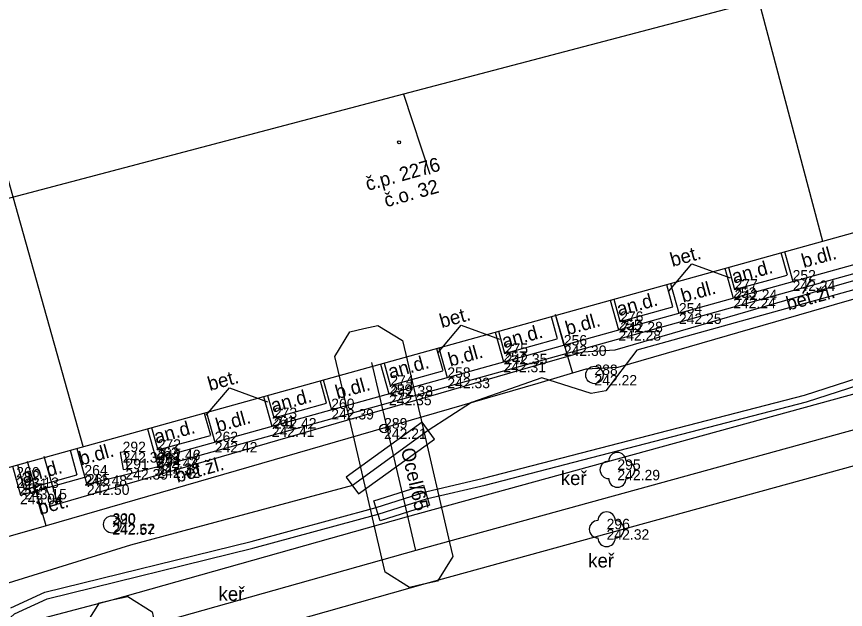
# Model space of a CAD drawing. Extents: x -599432 to -598680, y -1159407 to -1158632.
# Drawn here: x -599106.02 to -599082.18, y -1158901.06 to -1158883.99 of the extents above; entities that cross this region are included whole.
import ezdxf

# ---------------------------------------------------------------- set-up
doc = ezdxf.new("R2010")
doc.units = 0
for name, color, linetype in [('0004 VY - Body podrobné', 7, 'Continuous'), ('0005 VY - Body podrobné - čísla', 7, 'Continuous'), ('0006 VY - Body podrobné - výšky', 7, 'Continuous'), ('0007 ZA - Budova - zděná', 7, 'Continuous'), ('0010 ZA - Budova - označení', 7, 'Continuous'), ('0031 ZA - Ostatní rozhraní', 7, 'Continuous'), ('0032 TE - Popis povrchu', 7, 'Continuous'), ('0035 ZA - Strom - značka', 7, 'Continuous'), ('0036 TE - Strom - popis', 7, 'Continuous'), ('0049 TE - Orientační _ popisná čísla', 7, 'Continuous'), ('0075 ZA - BVK - kanalizace - buňky', 7, 'Continuous'), ('0092 ZA - RWE - plynovod - buňky', 7, 'Continuous'), ('0116 PV - budova převzatá z mapy', 7, 'Continuous'), ('0301 PV - RWE - popis', 7, 'Continuous'), ('0302 PV - RWE - NTL', 7, 'Continuous'), ('0303 PV - RWE - NTL přípojka', 7, 'Continuous'), ('0308 PV - RWE - ochranné pásmo', 7, 'Continuous'), ('0354 PV - EON - VN', 7, 'Continuous'), ('0367 PV - EON - VN chránička', 7, 'Continuous'), ('0454 PV - O2 - kabel zaměřený', 7, 'Continuous'), ('0454 PV - PODA -  vedeni budoucnost', 7, 'Continuous'), ('0455 PV - O2 - kabel nezaměřený', 7, 'Continuous'), ('0552 PV - NETBOX - vedení', 7, 'Continuous'), ('0553 PV - NETBOX - chranička', 7, 'Continuous')]:
    doc.layers.add(name, color=color, linetype=linetype)

msp = doc.modelspace()

# ---------------------------------------------------------------- linework, layer by layer
at = {"layer": '0004 VY - Body podrobné'}
for p, q in [((-599083.7, -1158891.59), (-599083.7, -1158891.59)), ((-599085.37, -1158891.85), (-599085.37, -1158891.85)), ((-599085.41, -1158892.09), (-599085.41, -1158892.09)), ((-599086.97, -1158892.54), (-599086.97, -1158892.54)), ((-599088.66, -1158892.78), (-599088.66, -1158892.78)), ((-599088.71, -1158893.02), (-599088.71, -1158893.02)), ((-599090.28, -1158893.46), (-599090.28, -1158893.46)), ((-599091.98, -1158893.7), (-599091.98, -1158893.7)), ((-599092.02, -1158893.93), (-599092.02, -1158893.93)), ((-599093.63, -1158894.39), (-599093.63, -1158894.39)), ((-599089.4, -1158894.31), (-599089.4, -1158894.31)), ((-599095.27, -1158894.62), (-599095.27, -1158894.62)), ((-599095.31, -1158894.88), (-599095.31, -1158894.88)), ((-599096.97, -1158895.29), (-599096.97, -1158895.29)), ((-599098.62, -1158895.55), (-599098.62, -1158895.55)), ((-599098.68, -1158895.79), (-599098.68, -1158895.79)), ((-599095.45, -1158895.85), (-599095.45, -1158895.85)), ((-599100.32, -1158896.24), (-599100.32, -1158896.24)), ((-599102.97, -1158896.53), (-599102.97, -1158896.53)), ((-599101.96, -1158896.46), (-599101.96, -1158896.46)), ((-599102.02, -1158896.69), (-599102.02, -1158896.69)), ((-599101.98, -1158896.85), (-599101.98, -1158896.85)), ((-599102.89, -1158897.02), (-599102.89, -1158897.02)), ((-599101.97, -1158896.97), (-599101.97, -1158896.97)), ((-599088.74, -1158897.04), (-599088.74, -1158897.04)), ((-599104.07, -1158897.2), (-599104.07, -1158897.2)), ((-599105.8, -1158897.59), (-599105.8, -1158897.59)), ((-599104, -1158897.46), (-599104, -1158897.46)), ((-599105.92, -1158897.73), (-599105.92, -1158897.73)), ((-599103.26, -1158898.59), (-599103.26, -1158898.59)), ((-599103.27, -1158898.61), (-599103.27, -1158898.61)), ((-599089.05, -1158898.75), (-599089.05, -1158898.75))]:
    msp.add_line(p, q, dxfattribs=at)
at = {"layer": '0007 ZA - Budova - zděná'}
msp.add_line((-599122.72, -1158901.55), (-599062.29, -1158884.74), dxfattribs=at)
at = {"layer": '0010 ZA - Budova - označení'}
msp.add_circle((-599095.018, -1158887.612), 0.0438, dxfattribs=at)
at = {"layer": '0031 ZA - Ostatní rozhraní'}
for p, q in [((-599102.013, -1158896.716), (-599063.128, -1158885.899)), ((-599101.946, -1158896.957), (-599063.061, -1158886.14)), ((-599084.036, -1158890.789), (-599083.859, -1158891.425)), ((-599083.931, -1158890.76), (-599083.692, -1158891.617)), ((-599085.647, -1158891.237), (-599085.409, -1158892.095)), ((-599085.548, -1158891.21), (-599085.371, -1158891.846)), ((-599085.369, -1158891.854), (-599083.856, -1158891.433)), ((-599087.211, -1158891.672), (-599086.973, -1158892.53)), ((-599087.329, -1158891.705), (-599087.152, -1158892.341)), ((-599088.842, -1158892.126), (-599088.665, -1158892.762)), ((-599088.95, -1158892.156), (-599088.712, -1158893.014)), ((-599088.663, -1158892.77), (-599087.15, -1158892.349)), ((-599090.648, -1158892.629), (-599090.472, -1158893.264)), ((-599090.521, -1158892.593), (-599090.283, -1158893.451)), ((-599092.258, -1158893.076), (-599092.019, -1158893.934)), ((-599092.161, -1158893.049), (-599091.984, -1158893.685)), ((-599091.982, -1158893.693), (-599090.469, -1158893.272)), ((-599093.94, -1158893.544), (-599093.763, -1158894.18)), ((-599093.871, -1158893.525), (-599093.632, -1158894.382)), ((-599095.557, -1158893.994), (-599095.318, -1158894.851)), ((-599095.452, -1158893.965), (-599095.275, -1158894.601)), ((-599095.273, -1158894.609), (-599093.761, -1158894.188)), ((-599097.289, -1158894.476), (-599097.112, -1158895.112)), ((-599097.203, -1158894.452), (-599096.965, -1158895.309)), ((-599098.919, -1158894.929), (-599098.681, -1158895.787)), ((-599098.802, -1158894.897), (-599098.625, -1158895.532)), ((-599098.623, -1158895.541), (-599097.11, -1158895.12)), ((-599100.624, -1158895.404), (-599100.447, -1158896.039)), ((-599100.558, -1158895.385), (-599100.319, -1158896.243)), ((-599102.252, -1158895.856), (-599101.946, -1158896.957)), ((-599102.137, -1158895.824), (-599101.958, -1158896.468)), ((-599101.958, -1158896.468), (-599100.445, -1158896.047)), ((-599104.289, -1158896.423), (-599104, -1158897.46)), ((-599104.48, -1158896.476), (-599104.284, -1158897.182)), ((-599105.993, -1158896.897), (-599105.797, -1158897.6)), ((-599106.14, -1158896.938), (-599105.91, -1158897.767)), ((-599101.946, -1158896.957), (-599104, -1158897.46)), ((-599105.91, -1158897.767), (-599104.058, -1158897.252)), ((-599105.796, -1158897.603), (-599104.284, -1158897.182))]:
    msp.add_line(p, q, dxfattribs=at)
at = {"layer": '0032 TE - Popis povrchu'}
for p, q in [((-599087.263, -1158891.899), (-599086.598, -1158891.108)), ((-599086.598, -1158891.108), (-599085.5, -1158891.512)), ((-599083.404, -1158891.961), (-599083.17, -1158891.554)), ((-599093.896, -1158893.662), (-599093.231, -1158892.871)), ((-599093.231, -1158892.871), (-599092.133, -1158893.275)), ((-599100.566, -1158895.47), (-599099.9, -1158894.679)), ((-599099.9, -1158894.679), (-599098.803, -1158895.082)), ((-599100.979, -1158896.916), (-599100.745, -1158896.508)), ((-599105.193, -1158897.499), (-599105.036, -1158897.898))]:
    msp.add_line(p, q, dxfattribs=at)
at = {"layer": '0035 ZA - Strom - značka'}
for centre in [(-599088.74, -1158897.04), (-599089.05, -1158898.75)]:
    msp.add_circle(centre, 0.00025, dxfattribs=at)
for centre, start, end in [((-599088.74, -1158896.79), 0, 180), ((-599088.99, -1158897.04), 90, 270), ((-599088.49, -1158897.04), 270, 90), ((-599088.74, -1158897.29), 180, 360), ((-599089.05, -1158898.5), 0, 180), ((-599089.3, -1158898.75), 90, 270), ((-599088.8, -1158898.75), 270, 90), ((-599089.05, -1158899), 180, 360)]:
    msp.add_arc(centre, 0.25, start, end, dxfattribs=at)
at = {"layer": '0075 ZA - BVK - kanalizace - buňky'}
msp.add_lwpolyline([(-599103.039, -1158896.541), (-599102.959, -1158897.031), (-599102.821, -1158897.009), (-599102.901, -1158896.519)], close=True, dxfattribs=at)
for centre in [(-599089.4, -1158894.31), (-599103.27, -1158898.61)]:
    msp.add_circle(centre, 0.25, dxfattribs=at)
at = {"layer": '0092 ZA - RWE - plynovod - buňky'}
msp.add_circle((-599095.45, -1158895.85), 0.125, dxfattribs=at)
at = {"layer": '0116 PV - budova převzatá z mapy'}
for p, q in [((-599086.46, -1158876.8), (-599082.837, -1158890.456)), ((-599104.106, -1158896.372), (-599107.93, -1158882.74))]:
    msp.add_line(p, q, dxfattribs=at)
at = {"layer": '0302 PV - RWE - NTL'}
msp.add_lwpolyline([(-599042.76, -1158885.49), (-599068.42, -1158892.17), (-599094.54, -1158899.36), (-599103.01, -1158901.75), (-599109.28, -1158903.4), (-599121.29, -1158906.57), (-599128.03, -1158908.44), (-599139.52, -1158911.687), (-599140.38, -1158911.93), (-599166.16, -1158919.18), (-599194.33, -1158927.1), (-599199.24, -1158928.46), (-599225.65, -1158935.9)], dxfattribs=at)
at = {"layer": '0303 PV - RWE - NTL přípojka'}
msp.add_lwpolyline([(-599094.54, -1158899.36), (-599095.36, -1158895.83), (-599095.8, -1158893.95)], dxfattribs=at)
at = {"layer": '0308 PV - RWE - ochranné pásmo'}
for points in [[(-599166.431, -1158918.217), (-599140.651, -1158910.968), (-599139.792, -1158910.725), (-599128.3, -1158907.477), (-599121.551, -1158905.605), (-599109.535, -1158902.433), (-599103.273, -1158900.785), (-599094.808, -1158898.397), (-599068.679, -1158891.204), (-599043.012, -1158884.522)], [(-599042.508, -1158886.458), (-599068.161, -1158893.136), (-599094.272, -1158900.323), (-599102.747, -1158902.715), (-599109.025, -1158904.367), (-599121.029, -1158907.535), (-599127.76, -1158909.403), (-599139.248, -1158912.649), (-599140.109, -1158912.892), (-599165.889, -1158920.143)]]:
    msp.add_lwpolyline(points, dxfattribs=at)
for points in [[(-599095.42, -1158899.989), (-599095.514, -1158899.586), (-599096.334, -1158896.057), (-599096.774, -1158894.178), (-599096.868, -1158893.775), (-599096.431, -1158893.07), (-599096.028, -1158892.976), (-599095.625, -1158892.882), (-599094.92, -1158893.319), (-599094.826, -1158893.722), (-599094.386, -1158895.603), (-599093.566, -1158899.134), (-599093.472, -1158899.537), (-599093.911, -1158900.24), (-599094.314, -1158900.334), (-599094.717, -1158900.428)], [(-599102.124, -1158901.128), (-599102.034, -1158901.532), (-599101.77, -1158902.713), (-599101.68, -1158903.117), (-599102.124, -1158903.817), (-599102.528, -1158903.907), (-599102.932, -1158903.997), (-599103.632, -1158903.553), (-599103.722, -1158903.149), (-599103.986, -1158901.968), (-599104.076, -1158901.564), (-599103.632, -1158900.864), (-599103.228, -1158900.774), (-599102.824, -1158900.684)]]:
    msp.add_lwpolyline(points, close=True, dxfattribs=at)
at = {"layer": '0354 PV - EON - VN'}
for points in [[(-599106.185, -1158901.015), (-599105.203, -1158900.565), (-599099.275, -1158899.103), (-599095.678, -1158898.124), (-599094.257, -1158897.674), (-599092.594, -1158897.283), (-599083.358, -1158894.894), (-599075.013, -1158892.195), (-599069.806, -1158890.267), (-599068.426, -1158889.707), (-599062.435, -1158887.486)], [(-599100.02, -1158930.068), (-599101.253, -1158923.926), (-599102.806, -1158918.536), (-599103.846, -1158916.105), (-599105.285, -1158911.524), (-599105.454, -1158911.165), (-599105.752, -1158909.781), (-599105.72, -1158909.453), (-599106.602, -1158905.369), (-599106.913, -1158903.886), (-599107.107, -1158903.206), (-599106.839, -1158901.863), (-599106.075, -1158901.185), (-599105.137, -1158900.755), (-599099.225, -1158899.297), (-599095.622, -1158898.316), (-599094.203, -1158897.866), (-599092.546, -1158897.477), (-599083.302, -1158895.086), (-599074.947, -1158892.385), (-599069.734, -1158890.453), (-599068.354, -1158889.893), (-599062.365, -1158887.674)]]:
    msp.add_lwpolyline(points, dxfattribs=at)
at = {"layer": '0367 PV - EON - VN chránička'}
for p, q in [((-599095.741, -1158897.934), (-599094.321, -1158897.484)), ((-599094.321, -1158897.484), (-599094.139, -1158898.056)), ((-599095.559, -1158898.506), (-599095.741, -1158897.934)), ((-599094.139, -1158898.056), (-599095.559, -1158898.506))]:
    msp.add_line(p, q, dxfattribs=at)
at = {"layer": '0454 PV - O2 - kabel zaměřený'}
for points in [[(-599044.86, -1158857.4), (-599039.92, -1158875.08), (-599038.76, -1158879.22), (-599057.85, -1158884.88), (-599061.72, -1158885.91), (-599062.01, -1158885.99), (-599082.28, -1158891.7), (-599088.81, -1158893.6), (-599089.73, -1158893.65), (-599091.17, -1158894.07)], [(-599091.17, -1158894.07), (-599104.83, -1158898.03), (-599105.23, -1158896.66)]]:
    msp.add_lwpolyline(points, dxfattribs=at)
at = {"layer": '0454 PV - PODA -  vedeni budoucnost'}
msp.add_line((-599090.528, -1158892.559), (-599090.032, -1158894.259), dxfattribs=at)
for points in [[(-599105.17, -1158898.649), (-599117.1, -1158902.075), (-599122.583, -1158904.816), (-599124.582, -1158905.375), (-599125.445, -1158902.506), (-599126.295, -1158901.085), (-599125.775, -1158896.452), (-599128.034, -1158888.659), (-599130.281, -1158879.673), (-599132.87, -1158880.447), (-599147.378, -1158884.773)], [(-599038.146, -1158879.559), (-599057.715, -1158885.361), (-599061.589, -1158886.393), (-599061.876, -1158886.472), (-599082.142, -1158892.181), (-599088.725, -1158894.096), (-599089.645, -1158894.146), (-599091.03, -1158894.55)], [(-599091.031, -1158894.55), (-599105.17, -1158898.649), (-599105.71, -1158896.8)]]:
    msp.add_lwpolyline(points, dxfattribs=at)
at = {"layer": '0455 PV - O2 - kabel nezaměřený'}
for points in [[(-599070.97, -1158879.92), (-599094.89, -1158886.23)], [(-599094.89, -1158886.23), (-599109.75, -1158890.15)], [(-599094.89, -1158886.23), (-599094.13, -1158888.53)]]:
    msp.add_lwpolyline(points, dxfattribs=at)
at = {"layer": '0552 PV - NETBOX - vedení'}
msp.add_lwpolyline([(-599081.59, -1158891.76), (-599088.18, -1158893.6), (-599088.18, -1158893.6), (-599089.07, -1158894.77), (-599089.07, -1158894.77), (-599089.49, -1158894.84), (-599089.49, -1158894.84), (-599090.91, -1158894.39), (-599090.91, -1158894.39), (-599092.94, -1158895.1), (-599092.94, -1158895.1), (-599094.18, -1158895.91), (-599094.18, -1158895.91), (-599096.36, -1158897.49), (-599096.36, -1158897.49), (-599102.74, -1158899.21), (-599102.74, -1158899.21), (-599108.37, -1158900.95)], dxfattribs=at)
at = {"layer": '0553 PV - NETBOX - chranička'}
msp.add_lwpolyline([(-599094.356, -1158895.667), (-599096.536, -1158897.247), (-599096.184, -1158897.733), (-599094.004, -1158896.153), (-599094.356, -1158895.667)], dxfattribs=at)

# ---------------------------------------------------------------- texts
at = {"layer": '0005 VY - Body podrobné - čísla'}
for s, p in [('252', (-599083.7, -1158891.59)), ('277', (-599085.37, -1158891.85)), ('253', (-599085.41, -1158892.09)), ('254', (-599086.97, -1158892.54)), ('276', (-599088.66, -1158892.78)), ('255', (-599088.71, -1158893.02)), ('256', (-599090.28, -1158893.46)), ('275', (-599091.98, -1158893.7)), ('257', (-599092.02, -1158893.93)), ('288', (-599089.4, -1158894.31)), ('258', (-599093.63, -1158894.39)), ('274', (-599095.27, -1158894.62)), ('259', (-599095.31, -1158894.88)), ('260', (-599096.97, -1158895.29)), ('273', (-599098.62, -1158895.55)), ('261', (-599098.68, -1158895.79)), ('289', (-599095.45, -1158895.85)), ('262', (-599100.32, -1158896.24)), ('272', (-599101.96, -1158896.46)), ('292', (-599102.97, -1158896.53)), ('263', (-599102.02, -1158896.69)), ('293', (-599101.98, -1158896.85)), ('294', (-599101.97, -1158896.97)), ('264', (-599104.07, -1158897.2)), ('291', (-599102.89, -1158897.02)), ('295', (-599088.74, -1158897.04)), ('266', (-599106.03, -1158897.26)), ('265', (-599104, -1158897.46)), ('271', (-599105.8, -1158897.59)), ('267', (-599105.92, -1158897.73)), ('290', (-599103.27, -1158898.61)), ('320', (-599103.26, -1158898.59)), ('296', (-599089.05, -1158898.75))]:
    msp.add_text(s, height=0.3, dxfattribs=at).set_placement(p)
at = {"layer": '0006 VY - Body podrobné - výšky'}
for s, p in [('242.24', (-599083.7, -1158891.89)), ('242.24', (-599085.37, -1158892.15)), ('242.24', (-599085.41, -1158892.39)), ('242.25', (-599086.97, -1158892.84)), ('242.28', (-599088.66, -1158893.08)), ('242.28', (-599088.71, -1158893.32)), ('242.30', (-599090.28, -1158893.76)), ('242.35', (-599091.98, -1158894)), ('242.31', (-599092.02, -1158894.23)), ('242.33', (-599093.63, -1158894.69)), ('242.22', (-599089.4, -1158894.61)), ('242.38', (-599095.27, -1158894.92)), ('242.35', (-599095.31, -1158895.18)), ('242.39', (-599096.97, -1158895.59)), ('242.42', (-599098.62, -1158895.85)), ('242.41', (-599098.68, -1158896.09)), ('242.21', (-599095.45, -1158896.15)), ('242.42', (-599100.32, -1158896.54)), ('242.39', (-599102.97, -1158896.83)), ('242.46', (-599101.96, -1158896.76)), ('242.43', (-599102.02, -1158896.99)), ('242.38', (-599101.98, -1158897.15)), ('242.39', (-599102.89, -1158897.32)), ('242.42', (-599101.97, -1158897.27)), ('242.29', (-599088.74, -1158897.34)), ('243.13', (-599106.03, -1158897.56)), ('242.48', (-599104.07, -1158897.5)), ('243.15', (-599105.8, -1158897.89)), ('242.50', (-599104, -1158897.76)), ('243.04', (-599105.92, -1158898.03)), ('242.62', (-599103.26, -1158898.89)), ('242.57', (-599103.27, -1158898.91)), ('242.32', (-599089.05, -1158899.05))]:
    msp.add_text(s, height=0.3, dxfattribs=at).set_placement(p)
at = {"layer": '0032 TE - Popis povrchu'}
for s, p in [('bet.', (-599087.159, -1158891.199)), ('b.dl.', (-599083.38, -1158891.232)), ('an.d.', (-599085.385, -1158891.685)), ('b.dl.', (-599086.85, -1158892.232)), ('bet.žl.', (-599083.821, -1158892.459)), ('an.d.', (-599088.694, -1158892.621)), ('bet.', (-599093.792, -1158892.962)), ('b.dl.', (-599090.174, -1158893.168)), ('an.d.', (-599091.998, -1158893.545)), ('b.dl.', (-599093.547, -1158894.072)), ('an.d.', (-599095.27, -1158894.421)), ('bet.', (-599100.461, -1158894.77)), ('b.dl.', (-599096.791, -1158895.008)), ('an.d.', (-599098.643, -1158895.397)), ('b.dl.', (-599100.229, -1158895.96)), ('an.d.', (-599102, -1158896.293)), ('b.dl.', (-599104.162, -1158896.917)), ('bet.žl.', (-599101.396, -1158897.414)), ('an.d.', (-599105.822, -1158897.442)), ('bet.', (-599105.35, -1158898.339))]:
    msp.add_text(s, height=0.4, rotation=15.5451, dxfattribs=at).set_placement(p)
at = {"layer": '0036 TE - Strom - popis'}
for p in [(-599090.369, -1158897.478), (-599089.579, -1158899.85), (-599100.211, -1158900.809)]:
    msp.add_text('keř', height=0.4, dxfattribs=at).set_placement(p)
at = {"layer": '0049 TE - Orientační _ popisná čísla'}
for s, p in [('č.p. 2276', (-599095.921, -1158889.013)), ('č.o. 32', (-599095.388, -1158889.486))]:
    msp.add_text(s, height=0.4, rotation=15.6438, dxfattribs=at).set_placement(p)
at = {"layer": '0301 PV - RWE - popis'}
msp.add_text('Ocel/65', height=0.4, rotation=283.0776, dxfattribs=at).set_placement((-599094.968, -1158896.455))

doc.saveas('drawing.dxf')
